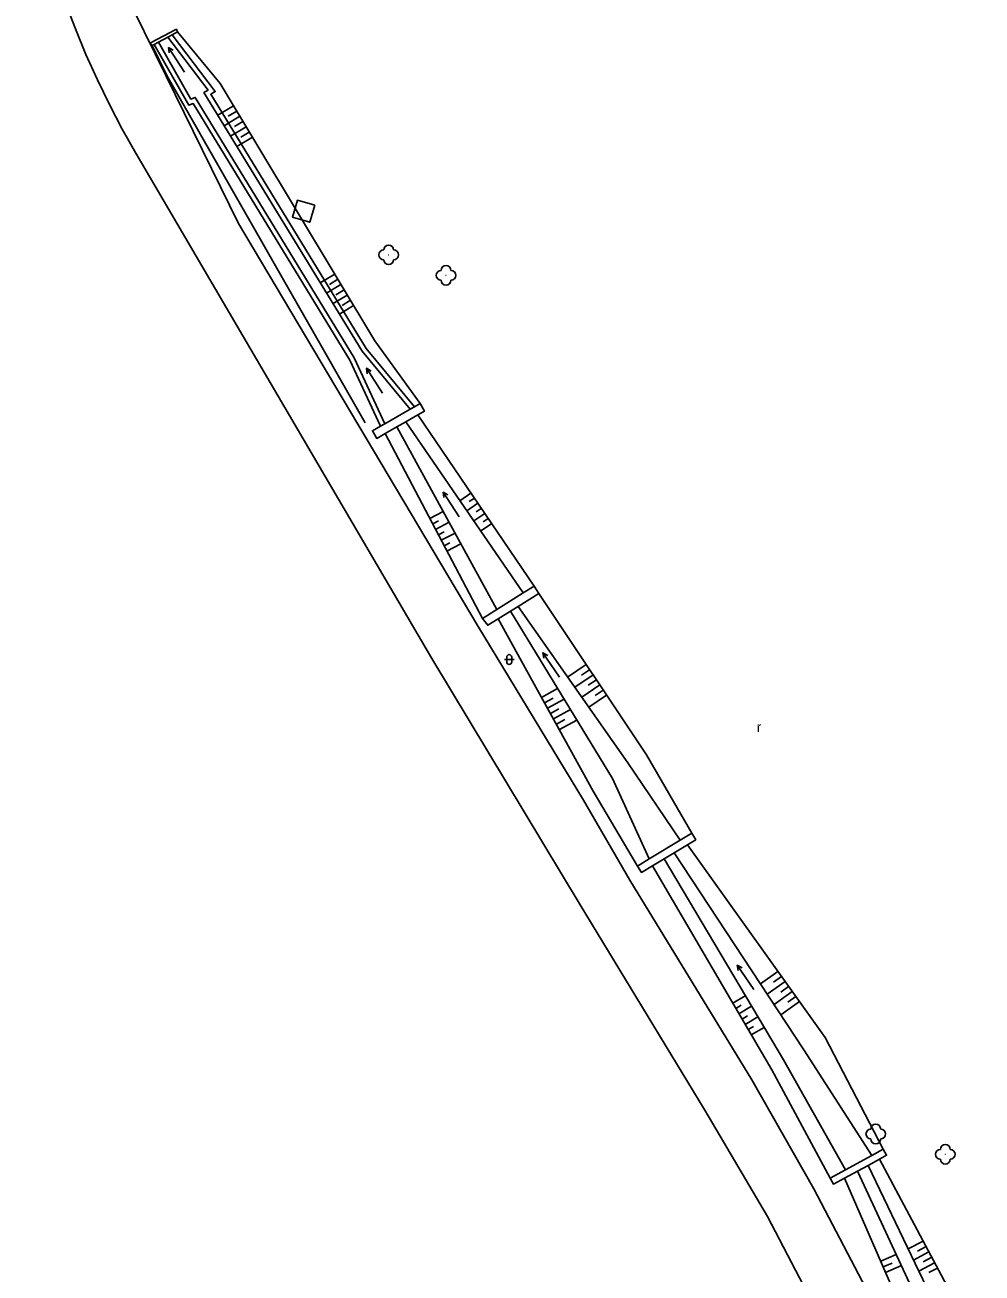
# Model space of a CAD drawing. Extents: x -582162 to -561283, y -1187583 to -1183539.
# Drawn here: x -571385.8 to -571288.3, y -1184524.5 to -1184397.3 of the extents above; entities that cross this region are included whole.
import ezdxf

# ---------------------------------------------------------------- set-up
doc = ezdxf.new("R2010")
doc.units = 0
for name, color, linetype in [('Vrstva 1', 7, 'Continuous'), ('Vrstva 10', 7, 'Continuous'), ('Vrstva 11', 7, 'Continuous'), ('Vrstva 12', 7, 'Continuous'), ('Vrstva 3', 7, 'Continuous'), ('Vrstva 4', 7, 'Continuous'), ('Vrstva 9', 7, 'Continuous')]:
    doc.layers.add(name, color=color, linetype=linetype)

# ---------------------------------------------------------------- blocks, each defined once
blk = doc.blocks.new('3.130')
at = {"layer": 'Vrstva 1'}
blk.add_circle((0, 0), 0.001, dxfattribs=at)
for centre, start, end in [((-1, 0), 90, 270), ((0, 1), 0, 180), ((1, 0), 270, 90), ((0, -1), 180, 360)]:
    blk.add_arc(centre, 1, start, end, dxfattribs=at)
blk = doc.blocks.new('3.019')
at = {"layer": 'Vrstva 1'}
blk.add_text('r', height=2, dxfattribs=at).set_placement((-0.496, -0.964))
blk = doc.blocks.new('3.160')
at = {"layer": 'Vrstva 1'}
for p, q in [((-1, 0), (1, 0)), ((-0.5, -0.5), (-0.5, 0.5)), ((0.5, -0.5), (0.5, 0.5))]:
    blk.add_line(p, q, dxfattribs=at)
for centre, start, end in [((0, 0.5), 0, 180), ((0, -0.5), 180, 360)]:
    blk.add_arc(centre, 0.5, start, end, dxfattribs=at)
blk = doc.blocks.new('8.021')
at = {"layer": 'Vrstva 1'}
blk.add_line((-3, 0), (3, 0), dxfattribs=at)
blk.add_lwpolyline([(2, 0.5), (3, 0), (2, -0.5)], dxfattribs=at)

msp = doc.modelspace()

# ---------------------------------------------------------------- linework, layer by layer
at = {"layer": 'Vrstva 10'}
for points in [[(-571300.02, -1184538.18), (-571310.15, -1184518.73), (-571316.55, -1184507.87), (-571329.25, -1184486.96), (-571344.39, -1184461.84), (-571374.55, -1184410.35), (-571375.93, -1184407.89), (-571377.23, -1184405.39), (-571378.46, -1184402.86), (-571379.63, -1184400.29), (-571380.71, -1184397.69), (-571381.73, -1184395.06), (-571382.67, -1184392.4), (-571383.53, -1184389.72), (-571383.89, -1184388.51), (-571385.85, -1184382.99)], [(-571378.84, -1184385.38), (-571377.03, -1184391.15), (-571371.47, -1184402.49)], [(-571370.83, -1184398.27), (-571370.29, -1184397.99)], [(-571372.92, -1184399.38), (-571372.69, -1184399.26)], [(-571372.69, -1184399.26), (-571370.83, -1184398.27)], [(-571371.47, -1184402.49), (-571364.1, -1184417.51), (-571339.66, -1184458.59), (-571328.91, -1184476.3), (-571324.2, -1184484.43), (-571311.77, -1184504.79), (-571305.46, -1184515.89), (-571295.19, -1184535.5)], [(-571356.32, -1184415.65), (-571358.07, -1184415.15), (-571358.57, -1184416.87), (-571356.82, -1184417.38), (-571356.32, -1184415.65)], [(-571349.61, -1184438.17), (-571350.43, -1184438.64), (-571349.99, -1184439.42), (-571349.13, -1184438.93), (-571347.93, -1184438.24), (-571347.03, -1184437.73), (-571345.79, -1184437.02), (-571345.14, -1184436.65), (-571345.58, -1184435.87), (-571346.15, -1184436.19)], [(-571346.15, -1184436.19), (-571346.59, -1184436.44), (-571349.17, -1184437.92), (-571349.61, -1184438.17)], [(-571339.23, -1184457.77), (-571338.68, -1184458.47), (-571337.61, -1184457.81), (-571336.37, -1184457.03), (-571335.59, -1184456.54), (-571333.49, -1184455.23), (-571333.96, -1184454.48), (-571335.08, -1184455.17), (-571337.75, -1184456.84), (-571339.23, -1184457.77)], [(-571317.89, -1184479.66), (-571319.06, -1184480.37), (-571322.23, -1184482.28), (-571323.41, -1184483), (-571323.01, -1184483.66), (-571321.88, -1184482.99), (-571320.69, -1184482.27), (-571319.67, -1184481.65), (-571318.32, -1184480.84), (-571317.48, -1184480.33), (-571317.89, -1184479.66)], [(-571303.78, -1184514.8), (-571302.22, -1184513.95), (-571299.54, -1184512.49), (-571298.37, -1184511.85), (-571298.03, -1184512.48), (-571298.74, -1184512.87), (-571299.92, -1184513.51), (-571300.98, -1184514.09), (-571302.31, -1184514.81), (-571303.44, -1184515.42), (-571303.78, -1184514.8)]]:
    msp.add_lwpolyline(points, dxfattribs=at)
at = {"layer": 'Vrstva 12'}
for points in [[(-571366.2, -1184406.48), (-571364.6, -1184405.52)], [(-571365.55, -1184407.55), (-571363.95, -1184406.59)], [(-571365.13, -1184406.57), (-571364.27, -1184406.06)], [(-571364.89, -1184408.62), (-571363.31, -1184407.66)], [(-571364.48, -1184407.64), (-571363.63, -1184407.13)], [(-571363.84, -1184408.71), (-571362.99, -1184408.2)], [(-571364.24, -1184409.68), (-571362.66, -1184408.73)], [(-571355.75, -1184423.55), (-571354.28, -1184422.67)], [(-571354.81, -1184423.72), (-571353.96, -1184423.2)], [(-571355.1, -1184424.62), (-571353.64, -1184423.74)], [(-571354.45, -1184425.68), (-571353, -1184424.81)], [(-571354.17, -1184424.79), (-571353.32, -1184424.27)], [(-571353.79, -1184426.75), (-571352.35, -1184425.88)], [(-571353.53, -1184425.86), (-571352.67, -1184425.34)], [(-571341.53, -1184445.77), (-571340.39, -1184444.99)], [(-571340.82, -1184446.8), (-571339.69, -1184446.03)], [(-571340.56, -1184445.86), (-571340.04, -1184445.51)], [(-571343.21, -1184446.87), (-571344.58, -1184447.59)], [(-571340.11, -1184447.83), (-571338.99, -1184447.06)], [(-571339.86, -1184446.9), (-571339.34, -1184446.55)], [(-571339.16, -1184447.93), (-571338.64, -1184447.58)], [(-571343.7, -1184447.83), (-571344.29, -1184448.14)], [(-571342.61, -1184447.97), (-571344, -1184448.7)], [(-571343.11, -1184448.94), (-571343.71, -1184449.25)], [(-571339.41, -1184448.86), (-571338.28, -1184448.1)], [(-571342.01, -1184449.06), (-571343.42, -1184449.8)], [(-571342.53, -1184450.05), (-571343.13, -1184450.36)], [(-571341.41, -1184450.16), (-571342.84, -1184450.91)], [(-571330.54, -1184463.74), (-571328.65, -1184462.47)], [(-571329.12, -1184463.54), (-571328.3, -1184462.99)], [(-571329.82, -1184464.76), (-571327.95, -1184463.51)], [(-571328.43, -1184464.58), (-571327.6, -1184464.03)], [(-571331.56, -1184464.91), (-571333.19, -1184465.82)], [(-571329.1, -1184465.78), (-571327.25, -1184464.55)], [(-571327.73, -1184465.62), (-571326.91, -1184465.07)], [(-571332.02, -1184465.88), (-571332.89, -1184466.36)], [(-571330.9, -1184465.98), (-571332.59, -1184466.91)], [(-571328.38, -1184466.81), (-571326.56, -1184465.59)], [(-571331.42, -1184466.98), (-571332.29, -1184467.46)], [(-571330.25, -1184467.05), (-571331.98, -1184468.01)], [(-571330.81, -1184468.07), (-571331.68, -1184468.55)], [(-571329.6, -1184468.12), (-571331.38, -1184469.1)], [(-571310.87, -1184495.02), (-571309.1, -1184493.75)], [(-571310.19, -1184496.07), (-571308.37, -1184494.77)], [(-571309.55, -1184494.84), (-571308.74, -1184494.26)], [(-571309.5, -1184497.11), (-571307.65, -1184495.79)], [(-571308.82, -1184495.86), (-571308.01, -1184495.28)], [(-571312.43, -1184496.23), (-571313.71, -1184496.98)], [(-571312.85, -1184497.2), (-571313.39, -1184497.52)], [(-571311.79, -1184497.3), (-571313.08, -1184498.06)], [(-571308.81, -1184498.16), (-571306.92, -1184496.81)], [(-571308.09, -1184496.87), (-571307.29, -1184496.3)], [(-571312.22, -1184498.28), (-571312.76, -1184498.6)], [(-571311.15, -1184498.38), (-571312.45, -1184499.14)], [(-571311.59, -1184499.36), (-571312.13, -1184499.68)], [(-571310.52, -1184499.45), (-571311.82, -1184500.22)], [(-571295.83, -1184522.03), (-571294.3, -1184521.22)], [(-571297.04, -1184522.6), (-571298.63, -1184523.29)], [(-571295.29, -1184523.16), (-571293.71, -1184522.32)], [(-571294.89, -1184522.24), (-571294.01, -1184521.77)], [(-571297.47, -1184523.47), (-571298.38, -1184523.86)], [(-571296.51, -1184523.73), (-571298.14, -1184524.44)], [(-571294.75, -1184524.29), (-571293.13, -1184523.43)], [(-571294.3, -1184523.34), (-571293.42, -1184522.87)], [(-571293.71, -1184524.44), (-571292.83, -1184523.98)]]:
    msp.add_lwpolyline(points, dxfattribs=at)
at = {"layer": 'Vrstva 4'}
for points in [[(-571372.92, -1184399.38), (-571373.06, -1184399.11), (-571370.42, -1184397.72), (-571370.29, -1184397.99)], [(-571349.61, -1184438.17), (-571352.73, -1184431.45), (-571368.7, -1184405.29), (-571369.15, -1184405.47), (-571372.69, -1184399.26)], [(-571370.83, -1184398.27), (-571366.45, -1184404.07), (-571366.92, -1184404.35), (-571351.07, -1184430.24), (-571346.15, -1184436.19)]]:
    msp.add_lwpolyline(points, dxfattribs=at)
at = {"layer": 'Vrstva 9'}
for points in [[(-571370.29, -1184397.99), (-571365.96, -1184403.25), (-571350.18, -1184429.48), (-571345.58, -1184435.87)], [(-571349.17, -1184437.92), (-571352.29, -1184431.21), (-571368.49, -1184404.67), (-571368.93, -1184404.84), (-571372.25, -1184399.02)], [(-571371.28, -1184398.51), (-571367.19, -1184403.92), (-571367.61, -1184404.17), (-571351.48, -1184430.53), (-571346.59, -1184436.44)], [(-571372.84, -1184399.43), (-571371.38, -1184402.44)], [(-571371.38, -1184402.44), (-571351.16, -1184437.82)], [(-571345.79, -1184437.02), (-571333.96, -1184454.48)], [(-571347.93, -1184438.24), (-571337.75, -1184456.84)], [(-571335.08, -1184455.17), (-571347.03, -1184437.73)], [(-571339.23, -1184457.77), (-571349.13, -1184438.93)], [(-571333.49, -1184455.23), (-571322.49, -1184471.67), (-571317.89, -1184479.66)], [(-571335.59, -1184456.54), (-571324.41, -1184472.48), (-571319.06, -1184480.37)], [(-571323.41, -1184483), (-571327.92, -1184475.36), (-571337.61, -1184457.81)], [(-571322.23, -1184482.28), (-571325.95, -1184474.09), (-571336.37, -1184457.03)], [(-571319.67, -1184481.65), (-571306.45, -1184501.74), (-571299.54, -1184512.49)], [(-571298.37, -1184511.85), (-571304.29, -1184500.49), (-571318.32, -1184480.84)], [(-571321.88, -1184482.99), (-571309.74, -1184503.77), (-571303.78, -1184514.8)], [(-571302.22, -1184513.95), (-571308.55, -1184502.77), (-571320.69, -1184482.27)], [(-571299.92, -1184513.51), (-571290.34, -1184533.5)], [(-571288.3, -1184532.51), (-571298.74, -1184512.87)], [(-571302.31, -1184514.81), (-571293.53, -1184535.04)], [(-571291.68, -1184534.15), (-571300.98, -1184514.09)]]:
    msp.add_lwpolyline(points, dxfattribs=at)

# ---------------------------------------------------------------- block references
at = {"layer": 'Vrstva 11', "xscale": 0.5, "yscale": 0.5}
for p in [(-571348.78, -1184420.71), (-571342.93, -1184422.8), (-571299.13, -1184510.31), (-571292.05, -1184512.38)]:
    msp.add_blockref('3.130', p, dxfattribs=at)
at = {"layer": 'Vrstva 3', "xscale": 0.5, "yscale": 0.5}
for p, rotation in [((-571370.4, -1184400.84), 122.76090743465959), ((-571350.23, -1184433.53), 122.76090743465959), ((-571342.41, -1184446.16), 122.76090743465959), ((-571332.21, -1184462.51), 124.34777887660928), ((-571312.4, -1184494.35), 124.34777895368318)]:
    msp.add_blockref('8.021', p, dxfattribs=dict(at, rotation=rotation))
for name, p in [('3.160', (-571336.49, -1184461.96)), ('3.019', (-571311.01, -1184468.85))]:
    msp.add_blockref(name, p, dxfattribs=at)

doc.saveas('drawing.dxf')
